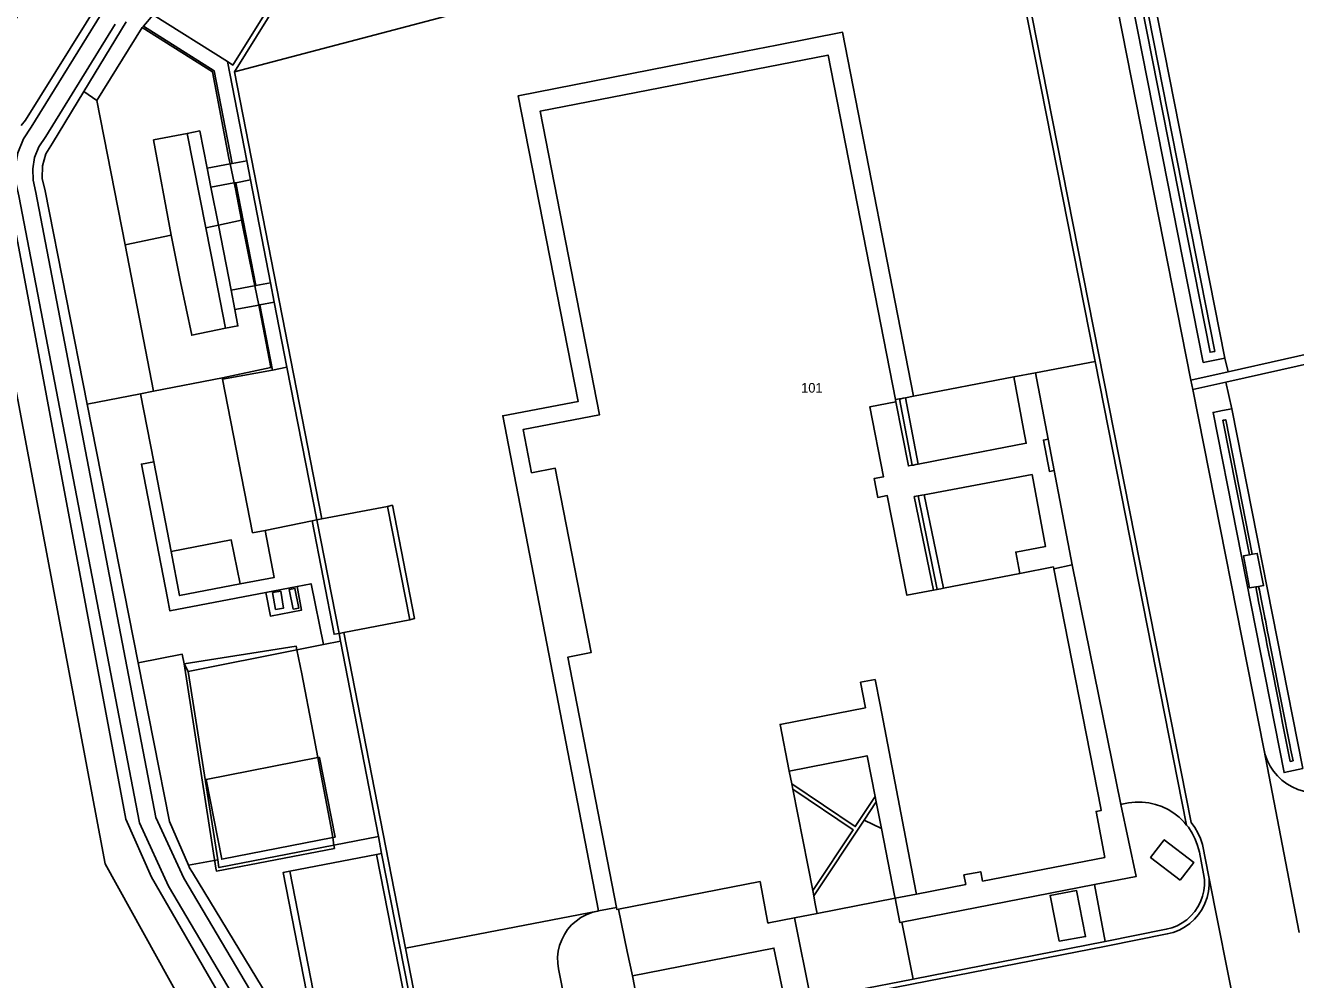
# Model space of a CAD drawing. Extents: x 152881 to 155736, y 382924 to 386919.
# Drawn here: x 154133.7 to 154265.7, y 383301.1 to 383400.4 of the extents above; entities that cross this region are included whole.
import ezdxf

# ---------------------------------------------------------------- set-up
doc = ezdxf.new("R2010")
doc.units = 0
for name, color, linetype in [('IMGEO_Groenvoorziening', 7, 'Continuous'), ('IMGEO_Hek', 7, 'Continuous'), ('IMGEO_Loofbos', 7, 'Continuous'), ('IMGEO_Open_loods', 7, 'Continuous'), ('IMGEO_Overkapping', 7, 'Continuous'), ('IMGEO_Pand', 7, 'Continuous'), ('IMGEO_Pand_nummerreeks', 7, 'Continuous'), ('IMGEO_Parkeervlak_gesloten', 7, 'Continuous'), ('IMGEO_Parkeervlak_open', 7, 'Continuous'), ('IMGEO_Rijbaan_lokaal_gesloten', 7, 'Continuous'), ('IMGEO_Rijbaan_lokaal_open', 7, 'Continuous'), ('IMGEO_Terreindeel_gesloten', 7, 'Continuous'), ('IMGEO_Voetpad_gesloten', 7, 'Continuous'), ('IMGEO_Voetpad_open', 7, 'Continuous'), ('IMGEO_Waterloop', 7, 'Continuous')]:
    doc.layers.add(name, color=color, linetype=linetype)

msp = doc.modelspace()

# ---------------------------------------------------------------- linework, layer by layer
at = {"layer": 'IMGEO_Groenvoorziening'}
for points in [[(154172.66, 383453.12), (154133.68, 383390.49), (154133.21, 383389.95)], [(154258.34, 383365.74), (154256.08, 383365.31), (154247.15, 383410.64)], [(154139.74, 383393.49), (154144.15, 383400.74)], [(154145.78, 383400.15), (154141.1, 383392.54)], [(154145.78, 383400.15), (154145.94, 383400.29)], [(154154.95, 383385.96), (154154.82, 383386.56), (154153.1, 383395.54), (154145.78, 383400.15)], [(154140.09, 383360.97), (154135.73, 383383.16), (154135.41, 383384.43), (154135.43, 383385.74), (154135.79, 383386.99), (154136.47, 383388.12), (154139.74, 383393.49)], [(154141.1, 383392.54), (154139.74, 383393.49)], [(154144.02, 383377.53), (154141.1, 383392.54)], [(154131.73, 383383.85), (154144.11, 383317.82), (154146.75, 383311.79), (154158.71, 383291.07), (154160.18, 383285.89), (154166.26, 383255.64), (154166.36, 383255.3), (154166.53, 383254.99), (154166.76, 383254.72), (154167.04, 383254.5), (154167.35, 383254.35), (154167.69, 383254.25), (154168.04, 383254.23), (154168.39, 383254.28), (154168.72, 383254.39), (154169.03, 383254.57), (154169.29, 383254.81), (154169.49, 383255.1), (154169.64, 383255.42), (154169.72, 383255.76), (154169.73, 383256.11), (154169.63, 383257.48)], [(154155.36, 383383.97), (154155.49, 383383.37), (154156.12, 383380.11), (154157.36, 383373.92), (154157.49, 383373.29)], [(154157.62, 383373.32), (154155.52, 383384)], [(154144.02, 383377.53), (154148.81, 383378.55)], [(154146.97, 383362.32), (154144.02, 383377.53)], [(154154.14, 383363.7), (154159.17, 383364.78), (154158.03, 383370.73), (154157.91, 383371.27)], [(154140.09, 383360.97), (154145.63, 383362.06)], [(154145.39, 383334.07), (154140.09, 383360.97)], [(154226.46, 383354.74), (154225.13, 383361.64)], [(154259.07, 383360.49), (154258.09, 383360.3), (154257.11, 383360.11), (154264.49, 383322.65), (154265.46, 383322.86), (154266.44, 383323.08)], [(154229.07, 383341.82), (154227.07, 383351.55)], [(154145.39, 383334.07), (154149.96, 383334.96), (154150.15, 383333.98), (154150.59, 383333.16)], [(154150.61, 383313.04), (154148.63, 383317.58), (154145.39, 383334.07)], [(154222.64, 383316.83), (154220.84, 383317.72)], [(154253.7, 383311.47), (154250.62, 383313.84), (154252.03, 383315.67), (154255.11, 383313.3), (154253.7, 383311.47)], [(154150.61, 383313.04), (154153.65, 383313.57)], [(154169.39, 383259.04), (154164.13, 383288.52), (154162.54, 383293.32), (154151.04, 383312.25), (154150.73, 383312.76), (154150.61, 383313.04)], [(154161.15, 383312.42), (154160.8, 383312.35), (154160.46, 383312.28), (154170.77, 383259.45), (154170.78, 383259.42)], [(154215.96, 383308.01), (154224.06, 383309.59)]]:
    msp.add_lwpolyline(points, dxfattribs=at)
at = {"layer": 'IMGEO_Hek'}
for points in [[(154141.1, 383392.54), (154145.78, 383400.15)], [(154145.78, 383400.15), (154153.1, 383395.54), (154154.82, 383386.56)], [(154144.02, 383377.53), (154141.1, 383392.54)], [(154154.82, 383386.56), (154154.95, 383385.96)], [(154154.95, 383385.96), (154155.36, 383383.97)], [(154155.36, 383383.97), (154155.49, 383383.37)], [(154155.49, 383383.37), (154156.12, 383380.11)], [(154153.72, 383379.58), (154152.41, 383379.29)], [(154156.12, 383380.11), (154153.72, 383379.58)], [(154156.12, 383380.11), (154157.36, 383373.92)], [(154148.81, 383378.55), (154144.02, 383377.53)], [(154144.02, 383377.53), (154146.97, 383362.32)], [(154157.36, 383373.92), (154157.49, 383373.29)], [(154157.49, 383373.29), (154157.91, 383371.27)], [(154158.03, 383370.73), (154159.17, 383364.78), (154154.14, 383363.7)], [(154157.91, 383371.27), (154158.03, 383370.73)], [(154161.88, 383335.42), (154161.8, 383335.81), (154150.15, 383333.98)], [(154163.53, 383326.98), (154162.4, 383332.92), (154161.88, 383335.42)], [(154150.15, 383333.98), (154153.47, 383312.72)], [(154164.05, 383324.21), (154163.53, 383326.98)], [(154164.27, 383323.07), (154164.05, 383324.21)], [(154165.41, 383317.08), (154164.27, 383323.07)], [(154165.6, 383315.89), (154165.41, 383317.08)], [(154165.73, 383315.11), (154165.6, 383315.89)], [(154153.47, 383312.72), (154153.52, 383312.42), (154165.79, 383314.75)], [(154165.79, 383314.75), (154165.73, 383315.11)]]:
    msp.add_lwpolyline(points, dxfattribs=at)
at = {"layer": 'IMGEO_Loofbos'}
for points in [[(154165.79, 383480.92), (154156.98, 383466.93), (154155.57, 383464.69), (154156.76, 383463.94), (154167.27, 383457.31), (154127.08, 383391.98), (154141.95, 383313.16), (154155.29, 383289.09), (154162.41, 383252.83), (154169.8, 383245.38), (154168.55, 383240.68), (154159.6, 383206.89)], [(154250.48, 383405.64), (154258.34, 383365.74)], [(154258.34, 383365.74), (154258.66, 383364.33)], [(154258.45, 383363.26), (154259.07, 383360.49)], [(154259.07, 383360.49), (154266.44, 383323.08)]]:
    msp.add_lwpolyline(points, dxfattribs=at)
at = {"layer": 'IMGEO_Open_loods'}
for points in [[(154164.47, 383349.03), (154171.29, 383350.34)], [(154171.29, 383350.34), (154173.61, 383338.55)], [(154163.95, 383348.95), (154164.47, 383349.03)], [(154166.26, 383337.13), (154163.95, 383348.95)], [(154173.61, 383338.55), (154166.76, 383337.24)], [(154166.76, 383337.24), (154166.26, 383337.13)], [(154164.05, 383324.21), (154152.44, 383321.95), (154154.07, 383313.64), (154165.6, 383315.89), (154165.84, 383315.94), (154164.22, 383324.24), (154164.05, 383324.21)]]:
    msp.add_lwpolyline(points, dxfattribs=at)
at = {"layer": 'IMGEO_Overkapping'}
msp.add_lwpolyline([(154241.11, 383305.11), (154243.86, 383305.6), (154242.92, 383310.38), (154240.17, 383309.89), (154241.11, 383305.11)], dxfattribs=at)
at = {"layer": 'IMGEO_Pand'}
for points in [[(154224.09, 383361.44), (154217.09, 383397.28), (154187.16, 383391.43), (154193.33, 383359.86), (154185.39, 383358.32), (154186.27, 383353.83), (154188.73, 383354.3), (154192.47, 383335.15), (154190.03, 383334.65), (154195.1, 383308.62)], [(154150.49, 383389.12), (154146.99, 383388.45), (154148.81, 383378.55)], [(154154.46, 383368.86), (154153.38, 383374.39), (154152.41, 383379.29), (154150.49, 383389.12)], [(154148.81, 383378.55), (154149.79, 383373.68), (154150.95, 383368.13), (154154.46, 383368.86)], [(154146.97, 383362.32), (154154.14, 383363.7)], [(154154.16, 383363.56), (154154.14, 383363.7)], [(154154.16, 383363.56), (154157.27, 383347.6), (154158.57, 383347.84)], [(154145.63, 383362.06), (154146.97, 383362.32)], [(154147, 383354.98), (154145.63, 383362.06)], [(154224.13, 383361.22), (154221.43, 383360.69), (154222.86, 383353.42), (154221.88, 383353.23), (154222.26, 383351.27), (154223.24, 383351.46), (154225.29, 383341.09), (154228.05, 383341.62)], [(154224.13, 383361.22), (154224.09, 383361.44)], [(154148.8, 383345.65), (154147, 383354.98)], [(154158.57, 383347.84), (154159.52, 383342.95), (154155.99, 383342.27)], [(154148.8, 383345.65), (154155.05, 383346.86), (154155.99, 383342.27)], [(154226.27, 383310.02), (154231.4, 383311.03), (154231.21, 383312.01), (154232.96, 383312.35), (154233.15, 383311.37), (154245.85, 383313.84), (154244.94, 383318.61), (154245.48, 383318.73), (154245.44, 383318.95), (154240.55, 383343.84)], [(154237.01, 383343.36), (154240.51, 383344.04), (154240.55, 383343.84)], [(154229.07, 383341.82), (154237.01, 383343.36)], [(154228.05, 383341.62), (154228.44, 383341.7)], [(154228.44, 383341.7), (154228.58, 383341.73), (154228.58, 383341.72), (154228.82, 383341.77), (154229.07, 383341.82)], [(154213.05, 383322.82), (154212.1, 383327.66), (154220.97, 383329.39), (154220.47, 383332.05), (154221.98, 383332.33), (154222.52, 383329.69), (154226.21, 383310.31), (154226.27, 383310.02)], [(154213.32, 383321.48), (154213.05, 383322.82)], [(154213.43, 383320.92), (154213.32, 383321.48)], [(154215.5, 383310.38), (154213.43, 383320.92)], [(154195.29, 383308.44), (154210.02, 383311.32), (154210.83, 383307), (154210.94, 383307.02), (154213.59, 383307.54)], [(154215.61, 383309.83), (154215.5, 383310.38)], [(154215.96, 383308.01), (154215.9, 383308.32), (154215.73, 383309.18), (154215.61, 383309.83)], [(154195.1, 383308.62), (154195.14, 383308.41), (154195.29, 383308.44)], [(154213.59, 383307.54), (154215.96, 383308.01)]]:
    msp.add_lwpolyline(points, dxfattribs=at)
at = {"layer": 'IMGEO_Parkeervlak_gesloten'}
for points in [[(154247.53, 383319.34), (154247.63, 383319.36), (154248.32, 383319.51), (154249.02, 383319.59), (154249.73, 383319.59), (154250.43, 383319.51), (154251.12, 383319.35), (154251.79, 383319.12), (154252.43, 383318.81), (154253.03, 383318.44), (154253.59, 383318.01), (154254.1, 383317.51), (154254.36, 383317.2)], [(154161.15, 383312.42), (154170.14, 383314.12)], [(154171.45, 383259.61), (154161.15, 383312.42)], [(154197.86, 383295.71), (154197.77, 383296.2), (154196.79, 383301.35), (154196.76, 383301.51)]]:
    msp.add_lwpolyline(points, dxfattribs=at)
at = {"layer": 'IMGEO_Parkeervlak_open'}
for points in [[(154245.89, 383305.1), (154244.77, 383311.01)], [(154224.77, 383307.09), (154225.94, 383301.18)]]:
    msp.add_lwpolyline(points, dxfattribs=at)
at = {"layer": 'IMGEO_Rijbaan_lokaal_gesloten'}
for points in [[(154155.4, 383395.53), (154196.05, 383460.87), (154196.36, 383461.43), (154196.59, 383462.02), (154196.76, 383462.63), (154196.86, 383463.26), (154196.88, 383463.89), (154196.83, 383464.53), (154196.71, 383465.15), (154196.52, 383465.76), (154196.26, 383466.34), (154195.93, 383466.88), (154195.55, 383467.39), (154195.11, 383467.84), (154194.62, 383468.24), (154194.08, 383468.59), (154193.51, 383468.87), (154189.75, 383471.3), (154189.53, 383470.86)], [(154256.66, 383311.83), (154256, 383315.18), (154255.79, 383315.8), (154255.52, 383316.39), (154255.2, 383316.95), (154254.82, 383317.48), (154235.61, 383414.95)], [(154177.92, 383401.47), (154231.81, 383411.97), (154232.39, 383412.11), (154232.94, 383412.32), (154233.48, 383412.59), (154233.97, 383412.92), (154234.43, 383413.3), (154234.84, 383413.73), (154235.21, 383414.2), (154244.84, 383365.41)], [(154244.83, 383414.15), (154254.81, 383363.47)], [(154155.4, 383395.53), (154177.92, 383401.47)], [(154193.23, 383308.27), (154183.28, 383359.76), (154191.1, 383361.24), (154184.88, 383393.05), (154206.38, 383397.26), (154211.76, 383398.31), (154218.59, 383399.65), (154225.98, 383361.8)], [(154164.47, 383349.03), (154155.4, 383395.53)], [(154244.84, 383365.41), (154238.65, 383364.22)], [(154236.4, 383363.81), (154225.98, 383361.8)], [(154238.65, 383364.22), (154236.4, 383363.81)], [(154255.01, 383362.49), (154254.81, 383363.47)], [(154262.37, 383325.11), (154255.01, 383362.49)], [(154173.61, 383338.55), (154174.12, 383338.68), (154171.81, 383350.46), (154171.29, 383350.34)], [(154159.65, 383339.63), (154159.35, 383341.38), (154160.2, 383341.52), (154160.5, 383339.77), (154159.65, 383339.63)], [(154173.17, 383304.39), (154166.76, 383337.24)], [(154266.05, 383306.02), (154262.37, 383325.11)], [(154262.37, 383325.11), (154262.53, 383324.49), (154262.75, 383323.89), (154263.05, 383323.33), (154263.4, 383322.8), (154263.81, 383322.31), (154264.27, 383321.87), (154264.78, 383321.49), (154265.33, 383321.17), (154265.91, 383320.91), (154266.52, 383320.72), (154266.96, 383320.63)], [(154256.66, 383311.83), (154259.53, 383297.34)], [(154173.17, 383304.39), (154193.13, 383308.25)], [(154193.13, 383308.25), (154192.53, 383308.1), (154191.95, 383307.87), (154191.4, 383307.58), (154190.89, 383307.22), (154190.43, 383306.81), (154190.02, 383306.34), (154189.68, 383305.82), (154189.4, 383305.27), (154189.18, 383304.69), (154189.04, 383304.08), (154188.98, 383303.47), (154188.99, 383302.85), (154189.07, 383302.23), (154189.77, 383298.75)], [(154193.23, 383308.27), (154193.13, 383308.25)], [(154181.89, 383255.16), (154182.03, 383256.05), (154182.11, 383256.96), (154182.11, 383257.86), (154182.05, 383258.76), (154181.91, 383259.66), (154173.17, 383304.39)]]:
    msp.add_lwpolyline(points, dxfattribs=at)
at = {"layer": 'IMGEO_Rijbaan_lokaal_open'}
for points in [[(154183.83, 383442.09), (154155.21, 383396.24), (154154.65, 383396.61)], [(154154.65, 383396.61), (154156.66, 383386.27)], [(154156.66, 383386.27), (154157.05, 383384.29)], [(154157.05, 383384.29), (154159.13, 383373.6)], [(154159.13, 383373.6), (154159.53, 383371.56)], [(154159.53, 383371.56), (154160.84, 383364.82)], [(154160.84, 383364.82), (154159.35, 383364.5)], [(154160.84, 383364.82), (154163.95, 383348.95)], [(154244.84, 383365.41), (154254.36, 383317.2)], [(154159.35, 383364.5), (154154.16, 383363.56)], [(154224.09, 383361.44), (154224.5, 383361.52)], [(154225.83, 383354.62), (154225.44, 383354.54), (154224.13, 383361.22)], [(154224.5, 383361.52), (154225.55, 383356.09), (154225.83, 383354.62)], [(154226.44, 383351.43), (154226.05, 383351.35), (154228.05, 383341.62)], [(154228.44, 383341.7), (154226.44, 383351.43)], [(154163.45, 383348.82), (154163.95, 383348.95)], [(154163.45, 383348.82), (154158.57, 383347.84)], [(154158.65, 383341.39), (154161.89, 383342.01)], [(154161.89, 383342.01), (154162.36, 383339.56), (154159.12, 383338.93), (154158.65, 383341.39)], [(154161.48, 383339.64), (154161.08, 383341.7), (154161.67, 383341.81), (154162.07, 383339.75), (154161.48, 383339.64)], [(154166.26, 383337.13), (154166.42, 383336.34)], [(154150.59, 383333.16), (154161.88, 383335.42), (154164.64, 383335.98)], [(154164.64, 383335.98), (154166.42, 383336.34)], [(154166.42, 383336.34), (154170.35, 383316.01)], [(154153.65, 383313.57), (154150.59, 383333.16)], [(154254.36, 383317.2), (154254.55, 383316.97), (154254.93, 383316.37), (154255.25, 383315.74), (154255.5, 383315.08), (154255.68, 383314.39), (154256.12, 383312.14), (154256.2, 383311.55), (154256.2, 383310.96), (154256.14, 383310.37), (154256, 383309.79), (154255.8, 383309.23), (154255.53, 383308.7), (154255.2, 383308.21), (154254.81, 383307.76), (154254.37, 383307.36), (154253.89, 383307.02), (154253.37, 383306.73), (154252.82, 383306.51), (154252.24, 383306.36), (154245.89, 383305.1)], [(154170.35, 383316.01), (154165.73, 383315.11), (154153.77, 383312.78), (154153.65, 383313.57)], [(154170.35, 383316.01), (154170.68, 383314.23)], [(154170.68, 383314.23), (154170.14, 383314.12)], [(154170.14, 383314.12), (154180.51, 383261.36)], [(154181.05, 383261.47), (154170.68, 383314.23)], [(154197.97, 383295.22), (154245.99, 383304.61), (154252.35, 383305.88), (154252.97, 383306.04), (154253.58, 383306.28), (154254.15, 383306.59), (154254.69, 383306.97), (154255.17, 383307.41), (154255.6, 383307.91), (154255.96, 383308.45), (154256.26, 383309.03), (154256.48, 383309.65), (154256.63, 383310.29), (154256.7, 383310.94), (154256.7, 383311.59), (154256.66, 383311.83)], [(154245.89, 383305.1), (154225.94, 383301.18)], [(154225.94, 383301.18), (154219.86, 383300), (154218.93, 383299.82), (154215.31, 383299.1)]]:
    msp.add_lwpolyline(points, dxfattribs=at)
at = {"layer": 'IMGEO_Terreindeel_gesloten'}
for points in [[(154261.55, 383341.97), (154260.91, 383341.86), (154260.27, 383345.2), (154260.89, 383345.31)], [(154261.18, 383345.36), (154261.7, 383345.45), (154262.35, 383342.1), (154261.84, 383342.02)]]:
    msp.add_lwpolyline(points, dxfattribs=at)
at = {"layer": 'IMGEO_Voetpad_gesloten'}
for points in [[(154240.58, 383354.08), (154240.09, 383353.98), (154239.47, 383357.24), (154239.96, 383357.33)], [(154239.96, 383357.33), (154240.58, 383354.08)], [(154166.26, 383337.13), (154165.74, 383337.04), (154163.45, 383348.82)]]:
    msp.add_lwpolyline(points, dxfattribs=at)
at = {"layer": 'IMGEO_Voetpad_open'}
for points in [[(154146.93, 383401.46), (154145.94, 383400.29)], [(154154.65, 383396.61), (154146.93, 383401.46)], [(154145.94, 383400.29), (154153.28, 383395.65), (154155.14, 383385.99)], [(154150.49, 383389.12), (154151.78, 383389.38), (154152.55, 383385.51)], [(154152.55, 383385.51), (154154.95, 383385.96)], [(154154.95, 383385.96), (154155.14, 383385.99)], [(154155.14, 383385.99), (154156.66, 383386.27)], [(154152.95, 383383.52), (154152.55, 383385.51)], [(154152.95, 383383.52), (154155.31, 383383.97), (154155.36, 383383.97)], [(154155.05, 383372.84), (154153.72, 383379.58), (154152.95, 383383.52)], [(154155.52, 383384), (154155.36, 383383.97)], [(154157.05, 383384.29), (154155.52, 383384)], [(154273.38, 383376.76), (154274.31, 383376.97), (154275.1, 383373.36), (154270.21, 383372.26), (154271.55, 383366.2), (154258.45, 383363.26)], [(154258.66, 383364.33), (154270.4, 383366.97), (154268.45, 383375.86), (154269.38, 383376.07)], [(154157.49, 383373.29), (154157.44, 383373.29), (154155.05, 383372.84)], [(154155.42, 383370.82), (154155.05, 383372.84)], [(154157.49, 383373.29), (154157.62, 383373.32)], [(154157.62, 383373.32), (154159.13, 383373.6)], [(154158.04, 383371.29), (154157.91, 383371.27)], [(154159.53, 383371.56), (154158.04, 383371.29)], [(154159.35, 383364.5), (154158.04, 383371.29)], [(154155.42, 383370.82), (154155.75, 383369.1), (154154.46, 383368.86)], [(154157.91, 383371.27), (154155.42, 383370.82)], [(154236.4, 383363.81), (154237.39, 383358.37), (154237.68, 383356.9), (154229.82, 383355.39), (154226.46, 383354.74)], [(154238.65, 383364.22), (154239.96, 383357.33)], [(154254.81, 383363.47), (154258.66, 383364.33)], [(154258.45, 383363.26), (154255.01, 383362.49)], [(154225.13, 383361.64), (154224.89, 383361.59), (154224.64, 383361.54), (154224.5, 383361.52)], [(154225.98, 383361.8), (154225.13, 383361.64)], [(154147, 383354.98), (154145.72, 383354.73), (154148.42, 383340.81), (154148.68, 383339.46), (154158.65, 383341.39)], [(154226.46, 383354.74), (154226.21, 383354.69), (154225.97, 383354.64), (154225.83, 383354.62)], [(154227.07, 383351.55), (154238.3, 383353.64), (154239.69, 383346.17), (154236.6, 383345.59), (154237.01, 383343.36)], [(154240.58, 383354.08), (154242.45, 383344.25)], [(154226.44, 383351.43), (154226.83, 383351.5), (154227.07, 383351.55), (154227.07, 383351.55)], [(154155.99, 383342.27), (154149.69, 383341.06), (154148.8, 383345.65)], [(154240.55, 383343.84), (154242.45, 383344.25)], [(154242.45, 383344.25), (154247.53, 383319.34)], [(154161.89, 383342.01), (154163.36, 383342.3), (154164.64, 383335.98)], [(154221.99, 383320.17), (154221.15, 383324.41), (154213.05, 383322.82)], [(154213.32, 383321.48), (154219.91, 383317.04), (154221.99, 383320.17)], [(154213.43, 383320.92), (154219.69, 383316.71), (154215.5, 383310.38)], [(154221.99, 383320.17), (154222.09, 383319.61)], [(154222.09, 383319.61), (154220.84, 383317.72)], [(154222.64, 383316.83), (154222.09, 383319.61)], [(154247.53, 383319.34), (154249.12, 383311.86), (154244.77, 383311.01)], [(154220.84, 383317.72), (154215.61, 383309.83)], [(154224.06, 383309.59), (154224, 383309.88), (154222.64, 383316.83)], [(154244.77, 383311.01), (154224.77, 383307.09)], [(154224.06, 383309.59), (154226.27, 383310.02)], [(154224.77, 383307.09), (154224.56, 383307.05), (154224.06, 383309.59)], [(154195.1, 383308.62), (154193.23, 383308.27)], [(154196.76, 383301.51), (154196.22, 383304.05), (154195.29, 383308.44)], [(154213.59, 383307.54), (154215.31, 383299.1)], [(154196.76, 383301.51), (154211.46, 383304.41), (154212.57, 383299.08), (154212.67, 383298.59)]]:
    msp.add_lwpolyline(points, dxfattribs=at)
at = {"layer": 'IMGEO_Waterloop'}
for points in [[(154168.91, 383256.39), (154169.1, 383255.38), (154167.33, 383255.04), (154161.28, 383286.99), (154159.77, 383291.86), (154148.53, 383310.84), (154145.51, 383317.42), (154132.97, 383382.62), (154132.65, 383384.03), (154132.61, 383385.58), (154132.88, 383387.11), (154133.45, 383388.56), (154134.25, 383389.78), (154172.9, 383452.21), (154185.41, 383469.69), (154181.35, 383472.2)], [(154249.42, 383406.37), (154257.28, 383366.46), (154256.79, 383366.36), (154248.03, 383410.83)], [(154143, 383400.49), (154135.77, 383388.81), (154135.06, 383387.73), (154134.62, 383386.62), (154134.42, 383385.45), (154134.45, 383384.26), (154134.73, 383382.99), (154147.23, 383317.98), (154150.13, 383311.68), (154161.43, 383292.59), (154163.03, 383287.42), (154168.28, 383259.69)], [(154260.89, 383345.31), (154258.13, 383359.29), (154258.28, 383359.32), (154258.43, 383359.35), (154261.18, 383345.36), (154261.18, 383345.36)], [(154260.89, 383345.31), (154261.04, 383345.34), (154261.18, 383345.36)], [(154261.84, 383342.02), (154261.92, 383341.63), (154262.11, 383340.68), (154262.2, 383340.18), (154262.48, 383338.8), (154262.49, 383338.73), (154262.54, 383338.49), (154262.78, 383337.28), (154262.93, 383336.51), (154262.98, 383336.25), (154263.15, 383335.4), (154263.25, 383334.88), (154263.6, 383333.11), (154263.92, 383331.48), (154264.26, 383329.72), (154265.12, 383325.37), (154265.17, 383325.13), (154265.42, 383323.88), (154265.27, 383323.84), (154265.12, 383323.81), (154264.34, 383327.79), (154263.96, 383329.72), (154263.06, 383334.27), (154262.94, 383334.88), (154262.71, 383336.05), (154262.67, 383336.25), (154262.62, 383336.51), (154262.36, 383337.84), (154262.18, 383338.73), (154262.17, 383338.8), (154261.81, 383340.63), (154261.8, 383340.68), (154261.55, 383341.96), (154261.55, 383341.97)], [(154261.84, 383342.02), (154261.69, 383341.99), (154261.55, 383341.97)]]:
    msp.add_lwpolyline(points, dxfattribs=at)

# ---------------------------------------------------------------- texts
at = {"layer": 'IMGEO_Pand_nummerreeks'}
msp.add_text('101', height=1, dxfattribs=at).set_placement((154214.29, 383362.17))

doc.saveas('drawing.dxf')
